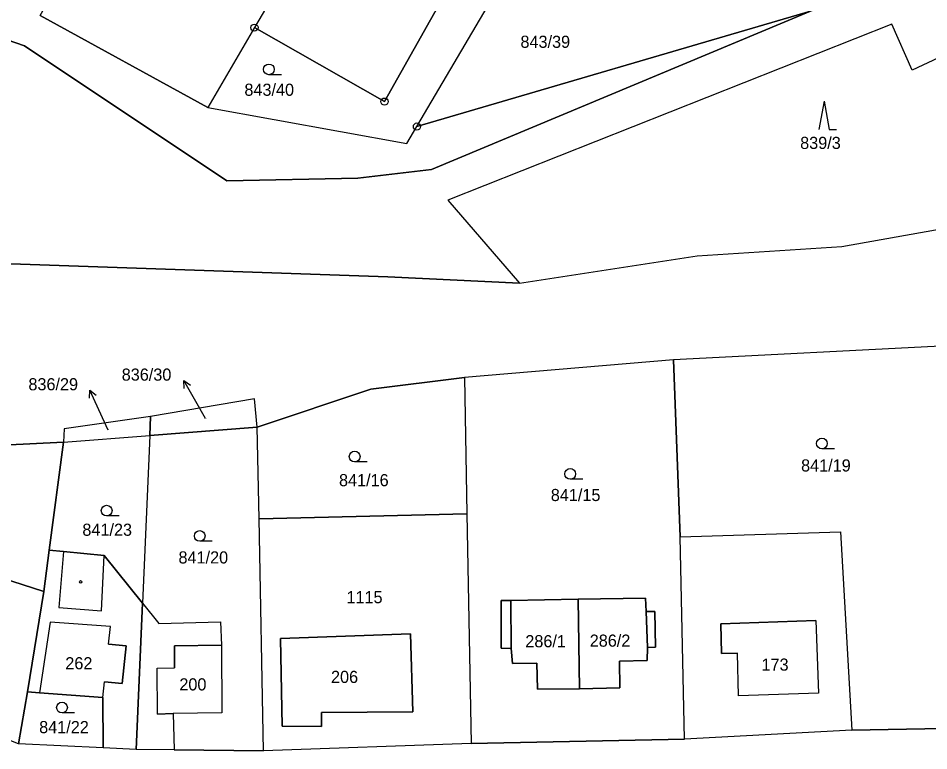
# Model space of a CAD drawing. Extents: x -654083 to -650132, y -1099819 to -1096699.
# Drawn here: x -652451.7 to -652324.2, y -1098431.8 to -1098329.1 of the extents above; entities that cross this region are included whole.
import ezdxf

# ---------------------------------------------------------------- set-up
doc = ezdxf.new("R2010")
doc.units = 0
for name, color, linetype in [('Geodetické body', 7, 'Continuous'), ('Hranice - vnitř_ kresba', 7, 'Continuous'), ('Obvody jako plochy', 7, 'Continuous'), ('Parcelní čísla', 7, 'Continuous'), ('Prvky pro prodl_ par_ č_', 7, 'Continuous'), ('Značky kultur', 7, 'Continuous'), ('Značky na budově ne v SPI', 7, 'Continuous')]:
    doc.layers.add(name, color=color, linetype=linetype)

msp = doc.modelspace()

# ---------------------------------------------------------------- linework, layer by layer
at = {"layer": 'Geodetické body'}
for centre, radius in [((-652418.64, -1098330.44), 0.5), ((-652418.64, -1098330.44), 0.001), ((-652400.43, -1098340.8), 0.5), ((-652400.43, -1098340.8), 0.001), ((-652395.89, -1098344.3), 0.5), ((-652395.89, -1098344.3), 0.001)]:
    msp.add_circle(centre, radius, dxfattribs=at)
at = {"layer": 'Hranice - vnitř_ kresba'}
for p, q in [((-652445.37, -1098403.85), (-652446.03, -1098411.71)), ((-652440.08, -1098412.17), (-652439.68, -1098404.41)), ((-652446.03, -1098411.71), (-652440.08, -1098412.17)), ((-652382.68, -1098417.43), (-652382.73, -1098410.7)), ((-652363.78, -1098412.26), (-652363.62, -1098417.29)), ((-652447.23, -1098413.77), (-652448.73, -1098423.66)), ((-652438.81, -1098414.37), (-652447.23, -1098413.77)), ((-652340.03, -1098413.51), (-652353.34, -1098414.01)), ((-652353.34, -1098414.01), (-652353.23, -1098418.13)), ((-652340.03, -1098413.51), (-652339.65, -1098423.72)), ((-652439.07, -1098416.83), (-652438.81, -1098414.37)), ((-652439.07, -1098416.83), (-652436.62, -1098417.06)), ((-652436.62, -1098417.06), (-652437.18, -1098422.35)), ((-652423.26, -1098416.99), (-652429.83, -1098417.09)), ((-652429.83, -1098417.09), (-652429.83, -1098420.13)), ((-652353.23, -1098418.13), (-652350.99, -1098418.1)), ((-652350.86, -1098424.1), (-652350.99, -1098418.1)), ((-652432.28, -1098420.18), (-652429.83, -1098420.13)), ((-652432.24, -1098426.64), (-652432.28, -1098420.18)), ((-652439.86, -1098424.33), (-652439.63, -1098422.13)), ((-652437.18, -1098422.35), (-652439.63, -1098422.13)), ((-652339.65, -1098423.72), (-652350.86, -1098424.1)), ((-652432.24, -1098426.64), (-652430.03, -1098426.55))]:
    msp.add_line(p, q, dxfattribs=at)
at = {"layer": 'Obvody jako plochy'}
for points in [[(-652729.64, -1098315.8), (-652661.4, -1098344.97), (-652637.26, -1098355.21), (-652619.41, -1098357.13), (-652535.49, -1098366.17), (-652531.67, -1098372.21), (-652478.52, -1098362.63), (-652399.95, -1098365.36), (-652381.5, -1098366.27), (-652356.63, -1098362.42), (-652336.38, -1098361.13), (-652302.52, -1098355.1), (-652297.55, -1098352.57), (-652267.15, -1098337.1), (-652238.2, -1098320.29), (-652228.97, -1098312.1), (-652236.44, -1098315.73), (-652243.27, -1098309.38), (-652247.49, -1098304.55), (-652246.48, -1098301.27)], [(-652186.79, -1098310.96), (-652202.08, -1098321.61), (-652206.66, -1098327.84), (-652210.39, -1098332.49), (-652211.78, -1098334.22), (-652218.22, -1098330.08), (-652253.24, -1098349.9), (-652272.67, -1098357.52), (-652318, -1098374.7), (-652321.64, -1098375.04), (-652359.97, -1098376.98), (-652389.22, -1098379.47), (-652402.32, -1098381.08), (-652418.27, -1098386.43), (-652418.63, -1098382.46), (-652433.19, -1098384.93), (-652445.3, -1098386.68), (-652445.4, -1098388.53), (-652462.43, -1098389.36)], [(-652448.63, -1098328.76), (-652425.17, -1098341.63), (-652397.28, -1098346.66), (-652395.89, -1098344.3), (-652340.76, -1098328.13), (-652393.84, -1098350.3), (-652404.15, -1098351.55), (-652422.5, -1098351.89), (-652450.84, -1098332.97), (-652463.05, -1098328.79)], [(-652187.92, -1098427.67), (-652195.29, -1098429.64), (-652205.53, -1098429.16), (-652215.03, -1098428.74), (-652221.7, -1098428.49), (-652248.96, -1098425.63), (-652253.48, -1098426.24), (-652265.82, -1098427.83), (-652267.72, -1098428.08), (-652280.25, -1098429.7), (-652283.17, -1098429.76), (-652286.13, -1098429.8), (-652309.66, -1098428.83), (-652317.1, -1098428.56), (-652334.99, -1098428.88), (-652358.4, -1098430.17), (-652388.3, -1098430.78), (-652417.36, -1098431.78), (-652429.9, -1098431.64), (-652435.22, -1098431.58), (-652439.83, -1098431.38), (-652451.7, -1098430.8), (-652473.23, -1098422.33)]]:
    msp.add_lwpolyline(points, dxfattribs=at)
for points in [[(-652434.06, -1098303.67), (-652430.89, -1098305.26), (-652410.52, -1098316.54), (-652412.21, -1098319.43), (-652418.64, -1098330.44), (-652425.17, -1098341.63), (-652448.63, -1098328.76), (-652442.29, -1098317.57), (-652434.27, -1098303.56)], [(-652380.75, -1098305.83), (-652383.38, -1098310.49), (-652400.43, -1098340.8), (-652418.64, -1098330.44), (-652425.17, -1098341.63), (-652397.28, -1098346.66), (-652395.89, -1098344.3), (-652375.14, -1098308.96)], [(-652383.38, -1098310.49), (-652386.31, -1098309.03), (-652390.96, -1098317.48), (-652399.83, -1098312.49), (-652405.83, -1098323.09), (-652407.14, -1098322.34), (-652410.49, -1098320.42), (-652412.21, -1098319.43), (-652418.64, -1098330.44), (-652400.43, -1098340.8)], [(-652362.69, -1098315.92), (-652340.76, -1098328.13), (-652395.89, -1098344.3), (-652375.14, -1098308.96)], [(-652338.05, -1098327), (-652330.4, -1098325.42), (-652327.75, -1098326.79), (-652313.3, -1098325.37), (-652311.1, -1098329.18), (-652326.52, -1098336.41), (-652329.39, -1098329.93), (-652391.55, -1098354.62), (-652381.5, -1098366.27), (-652399.95, -1098365.36), (-652478.52, -1098362.63), (-652531.67, -1098372.21), (-652535.49, -1098366.17), (-652545.7, -1098345.51), (-652546.92, -1098343), (-652518.45, -1098354.28), (-652508.1, -1098348.73), (-652482.03, -1098339.62), (-652463.05, -1098328.79), (-652450.84, -1098332.97), (-652422.5, -1098351.89), (-652404.15, -1098351.55), (-652393.84, -1098350.3), (-652340.76, -1098328.13)], [(-652302.52, -1098355.1), (-652297.55, -1098352.57), (-652311.1, -1098329.18), (-652326.52, -1098336.41), (-652329.39, -1098329.93), (-652391.55, -1098354.62), (-652381.5, -1098366.27), (-652356.63, -1098362.42), (-652336.38, -1098361.13)], [(-652321.64, -1098375.04), (-652359.97, -1098376.98), (-652359, -1098401.81), (-652336.58, -1098401.09), (-652334.99, -1098428.88), (-652317.1, -1098428.56)], [(-652359.97, -1098376.98), (-652389.22, -1098379.47), (-652388.92, -1098398.59), (-652388.3, -1098430.78), (-652358.4, -1098430.17), (-652359, -1098401.81)], [(-652389.22, -1098379.47), (-652388.92, -1098398.59), (-652417.96, -1098399.29), (-652418.27, -1098386.43), (-652402.32, -1098381.08)], [(-652418.63, -1098382.46), (-652433.19, -1098384.93), (-652433.29, -1098387.58), (-652418.27, -1098386.43)], [(-652445.3, -1098386.68), (-652445.4, -1098388.53), (-652433.29, -1098387.58), (-652433.19, -1098384.93)], [(-652432.02, -1098413.94), (-652423.39, -1098413.7), (-652423.26, -1098416.99), (-652423.2, -1098426.44), (-652430.03, -1098426.55), (-652429.9, -1098431.64), (-652417.36, -1098431.78), (-652417.96, -1098399.29), (-652418.27, -1098386.43), (-652433.29, -1098387.58), (-652434.32, -1098411.08)], [(-652447.39, -1098403.65), (-652448.15, -1098409.45), (-652461.62, -1098405.13), (-652466.24, -1098403.65), (-652466.66, -1098403.51), (-652462.43, -1098389.36), (-652445.4, -1098388.53)], [(-652433.29, -1098387.58), (-652434.32, -1098411.08), (-652439.68, -1098404.41), (-652445.37, -1098403.85), (-652447.39, -1098403.65), (-652445.4, -1098388.53)], [(-652388.92, -1098398.59), (-652388.3, -1098430.78), (-652417.36, -1098431.78), (-652417.96, -1098399.29)], [(-652359, -1098401.81), (-652336.58, -1098401.09), (-652334.99, -1098428.88), (-652358.4, -1098430.17)], [(-652448.15, -1098409.45), (-652450.42, -1098423.53), (-652451.7, -1098430.8), (-652473.23, -1098422.33), (-652467.37, -1098405.54), (-652466.66, -1098403.51), (-652466.24, -1098403.65), (-652461.62, -1098405.13)], [(-652447.39, -1098403.65), (-652445.37, -1098403.85), (-652439.68, -1098404.41), (-652434.32, -1098411.08), (-652435.22, -1098431.58), (-652439.83, -1098431.38), (-652439.86, -1098424.33), (-652448.73, -1098423.66), (-652450.42, -1098423.53), (-652448.15, -1098409.45)], [(-652363.64, -1098419.12), (-652367.5, -1098419.24), (-652367.49, -1098422.96), (-652373.14, -1098423.09), (-652379, -1098423.15), (-652379.08, -1098419.49), (-652382.51, -1098419.56), (-652382.68, -1098417.43), (-652384.07, -1098417.42), (-652384.11, -1098410.73), (-652382.73, -1098410.7), (-652373.32, -1098410.55), (-652363.88, -1098410.39), (-652363.78, -1098412.26), (-652362.59, -1098412.25), (-652362.47, -1098417.25), (-652363.62, -1098417.29)], [(-652373.14, -1098423.09), (-652367.49, -1098422.96), (-652367.5, -1098419.24), (-652363.64, -1098419.12), (-652363.62, -1098417.29), (-652362.47, -1098417.25), (-652362.59, -1098412.25), (-652363.78, -1098412.26), (-652363.88, -1098410.39), (-652373.32, -1098410.55)], [(-652373.14, -1098423.09), (-652367.49, -1098422.96), (-652367.5, -1098419.24), (-652363.64, -1098419.12), (-652363.62, -1098417.29), (-652363.78, -1098412.26), (-652363.88, -1098410.39), (-652373.32, -1098410.55)], [(-652423.39, -1098413.7), (-652423.26, -1098416.99), (-652423.2, -1098426.44), (-652430.03, -1098426.55), (-652429.9, -1098431.64), (-652435.22, -1098431.58), (-652434.32, -1098411.08), (-652432.02, -1098413.94)], [(-652384.07, -1098417.42), (-652382.68, -1098417.43), (-652382.51, -1098419.56), (-652379.08, -1098419.49), (-652379, -1098423.15), (-652373.14, -1098423.09), (-652373.32, -1098410.55), (-652382.73, -1098410.7), (-652384.11, -1098410.73)], [(-652379, -1098423.15), (-652373.14, -1098423.09), (-652373.32, -1098410.55), (-652382.73, -1098410.7), (-652382.68, -1098417.43), (-652382.51, -1098419.56), (-652379.08, -1098419.49)], [(-652448.73, -1098423.66), (-652439.86, -1098424.33), (-652439.63, -1098422.13), (-652437.18, -1098422.35), (-652436.62, -1098417.06), (-652439.07, -1098416.83), (-652438.81, -1098414.37), (-652447.23, -1098413.77)], [(-652350.86, -1098424.1), (-652350.99, -1098418.1), (-652353.23, -1098418.13), (-652353.34, -1098414.01), (-652340.03, -1098413.51), (-652339.65, -1098423.72)], [(-652409.27, -1098426.42), (-652396.46, -1098426.32), (-652396.78, -1098415.38), (-652415, -1098416.04), (-652414.77, -1098428.33), (-652409.23, -1098428.36)], [(-652396.46, -1098426.32), (-652396.78, -1098415.38), (-652415, -1098416.04), (-652414.77, -1098428.33), (-652409.23, -1098428.36), (-652409.27, -1098426.42)], [(-652415, -1098416.04), (-652396.78, -1098415.38), (-652396.46, -1098426.32), (-652409.27, -1098426.42), (-652409.23, -1098428.36), (-652414.77, -1098428.33)], [(-652423.26, -1098416.99), (-652423.2, -1098426.44), (-652430.03, -1098426.55), (-652432.24, -1098426.64), (-652432.28, -1098420.18), (-652429.83, -1098420.13), (-652429.83, -1098417.09)], [(-652448.73, -1098423.66), (-652439.86, -1098424.33), (-652439.83, -1098431.38), (-652451.7, -1098430.8), (-652450.42, -1098423.53)]]:
    msp.add_lwpolyline(points, close=True, dxfattribs=at)
at = {"layer": 'Prvky pro prodl_ par_ č_'}
for p, q in [((-652427.06, -1098382.51), (-652428.55, -1098379.91)), ((-652440.44, -1098383.99), (-652441.69, -1098381.26)), ((-652425.5, -1098385.23), (-652427.06, -1098382.51)), ((-652439.14, -1098386.83), (-652440.44, -1098383.99))]:
    msp.add_line(p, q, dxfattribs=at)
for points in [[(-652428.49, -1098381.02), (-652428.55, -1098379.91), (-652427.62, -1098380.53)], [(-652441.73, -1098382.38), (-652441.69, -1098381.26), (-652440.82, -1098381.96)]]:
    msp.add_lwpolyline(points, dxfattribs=at)
at = {"layer": 'Značky kultur'}
for p, q in [((-652414.87, -1098337.04), (-652416.62, -1098337.04)), ((-652338.87, -1098340.73), (-652339.6, -1098344.73)), ((-652338.87, -1098340.73), (-652338.14, -1098344.73)), ((-652338.14, -1098344.73), (-652337.14, -1098344.73)), ((-652337.42, -1098389.47), (-652339.17, -1098389.47)), ((-652402.86, -1098391.3), (-652404.61, -1098391.3)), ((-652372.67, -1098393.73), (-652374.42, -1098393.73)), ((-652437.59, -1098398.87), (-652439.34, -1098398.87)), ((-652424.56, -1098402.42), (-652426.31, -1098402.42)), ((-652443.84, -1098426.47), (-652445.59, -1098426.47))]:
    msp.add_line(p, q, dxfattribs=at)
for centre in [(-652416.62, -1098336.29), (-652339.17, -1098388.72), (-652404.61, -1098390.55), (-652374.42, -1098392.98), (-652439.34, -1098398.12), (-652426.31, -1098401.67), (-652445.59, -1098425.72)]:
    msp.add_circle(centre, 0.75, dxfattribs=at)
at = {"layer": 'Značky na budově ne v SPI'}
msp.add_circle((-652442.99, -1098408.11), 0.175, dxfattribs=at)

# ---------------------------------------------------------------- texts
at = {"layer": 'Parcelní čísla'}
for s, height, p in [('843/39', 1.7, (-652381.39, -1098333.27)), ('843/40', 1.7, (-652420.05, -1098339.99)), ('839/3', 1.7, (-652342.22, -1098347.44)), ('836/30', 0.1, (-652425.73, -1098385.23)), ('836/29', 0.1, (-652439.36, -1098386.83)), ('841/19', 1.7, (-652342.09, -1098392.64)), ('841/16', 1.7, (-652406.8, -1098394.7)), ('841/15', 1.7, (-652377.14, -1098396.78)), ('841/23', 1.7, (-652442.74, -1098401.65)), ('841/20', 1.7, (-652429.28, -1098405.53)), ('1115', 1.7, (-652405.76, -1098411.1)), ('286/1', 1.7, (-652380.71, -1098417.27)), ('286/2', 1.7, (-652371.69, -1098417.19)), ('262', 1.7, (-652445.13, -1098420.36)), ('173', 1.7, (-652347.63, -1098420.55)), ('206', 1.7, (-652407.92, -1098422.27)), ('200', 1.7, (-652429.16, -1098423.32)), ('841/22', 1.7, (-652448.79, -1098429.31))]:
    msp.add_text(s, height=height, dxfattribs=at).set_placement(p)
at = {"layer": 'Prvky pro prodl_ par_ č_'}
for s, p in [('836/30', (-652437.23, -1098379.91)), ('836/29', (-652450.3, -1098381.26))]:
    msp.add_text(s, height=1.7, dxfattribs=at).set_placement(p)

doc.saveas('drawing.dxf')
